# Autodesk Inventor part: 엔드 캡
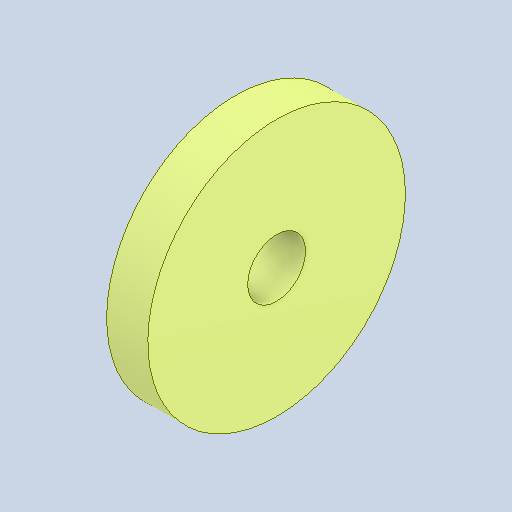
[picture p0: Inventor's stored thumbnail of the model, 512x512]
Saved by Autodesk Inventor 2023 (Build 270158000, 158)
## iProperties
Created: 2026-03
Part Number: 엔드 캡
Material: 강철, 연강
Document SubType Name: Modeling
Designer: 4강의실
Density: 7.85 g/cm^3
Appearance: 기본값
Author: jhkim
Sending System: Autodesk Inventor 2026
Preprocessor: ST-DEVELOPER v20.1
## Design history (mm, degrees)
feature "솔리드1"
node "솔리드2"
